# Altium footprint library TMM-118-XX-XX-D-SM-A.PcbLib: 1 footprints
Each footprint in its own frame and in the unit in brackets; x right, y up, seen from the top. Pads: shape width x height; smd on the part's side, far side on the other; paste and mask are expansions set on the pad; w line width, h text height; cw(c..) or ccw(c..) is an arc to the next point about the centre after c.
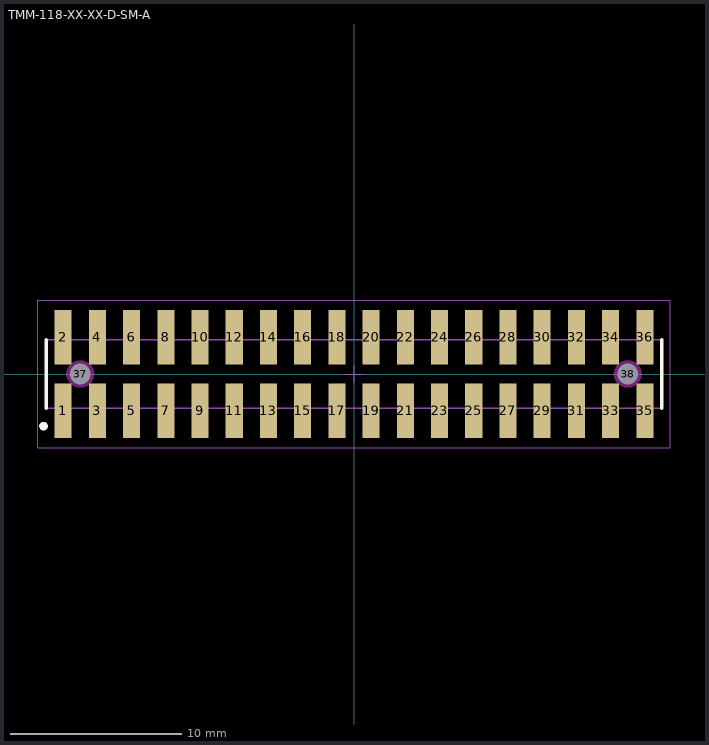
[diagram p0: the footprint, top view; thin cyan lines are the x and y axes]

## TMM-118-XX-XX-D-SM-A [mm] "2.00mm pitch, 36 pin, terminal strip; double row, w/alignment pins, SMT"
height 2.77
pads (38):
  rect 1x3.2 smd mask+0: 1(-17,-2.15) 2(-17,2.15) 3(-15,-2.15) 4(-15,2.15) 5(-13,-2.15) 6(-13,2.15) 7(-11,-2.15) 8(-11,2.15) 9(-9,-2.15) 10(-9,2.15) 11(-7,-2.15) 12(-7,2.15) 13(-5,-2.15) 14(-5,2.15) 15(-3,-2.15) 16(-3,2.15) 17(-1,-2.15) 18(-1,2.15) 19(1,-2.15) 20(1,2.15) 21(3,-2.15) 22(3,2.15) 23(5,-2.15) 24(5,2.15) 25(7,-2.15) 26(7,2.15) 27(9,-2.15) 28(9,2.15) 29(11,-2.15) 30(11,2.15) 31(13,-2.15) 32(13,2.15) 33(15,-2.15) 34(15,2.15) 35(17,-2.15) 36(17,2.15)
  round 1 hole 1.2 unplated mask+0: 37(-16,0) 38(16,0)
Top Overlay:
  circle w0.25: c-18.15,-3.05 r0.125
  lines w0.2: -18,-2 -18,2 ; 18,-2 18,2
Keep-Out Layer:
  pour cut-out: -15.193,0 -15.221,0.209 -15.301,0.403 -15.429,0.571 -15.597,0.699 -15.791,0.779 -16,0.807 -16.209,0.779 -16.403,0.699 -16.571,0.571 -16.699,0.403 -16.779,0.209 -16.807,0 -16.779,-0.209 -16.699,-0.403 -16.571,-0.571 -16.403,-0.699 -16.209,-0.779 -16,-0.807 -15.791,-0.779 -15.597,-0.699 -15.429,-0.571 -15.301,-0.403 -15.221,-0.209
  pour cut-out: 16.807,0 16.779,0.209 16.699,0.403 16.571,0.571 16.403,0.699 16.209,0.779 16,0.807 15.791,0.779 15.597,0.699 15.429,0.571 15.301,0.403 15.221,0.209 15.193,0 15.221,-0.209 15.301,-0.403 15.429,-0.571 15.597,-0.699 15.791,-0.779 16,-0.807 16.209,-0.779 16.403,-0.699 16.571,-0.571 16.699,-0.403 16.779,-0.209
Mechanical 12:
  lines w0.001: -18,-2 18,-2 18,2 -18,2 -18,-2
Mechanical 13:
  lines w0.1: -18,-2 18,-2 18,2 -18,2 -18,-2
  text ".Designator" at 0,-0.127 h1.52
Mechanical 15:
  lines w0.05: -0.5,0 0.5,0 ; 0,-0.5 0,0.5 ; -18.5,-4.3 18.5,-4.3 18.5,4.3 -18.5,4.3 -18.5,-4.3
